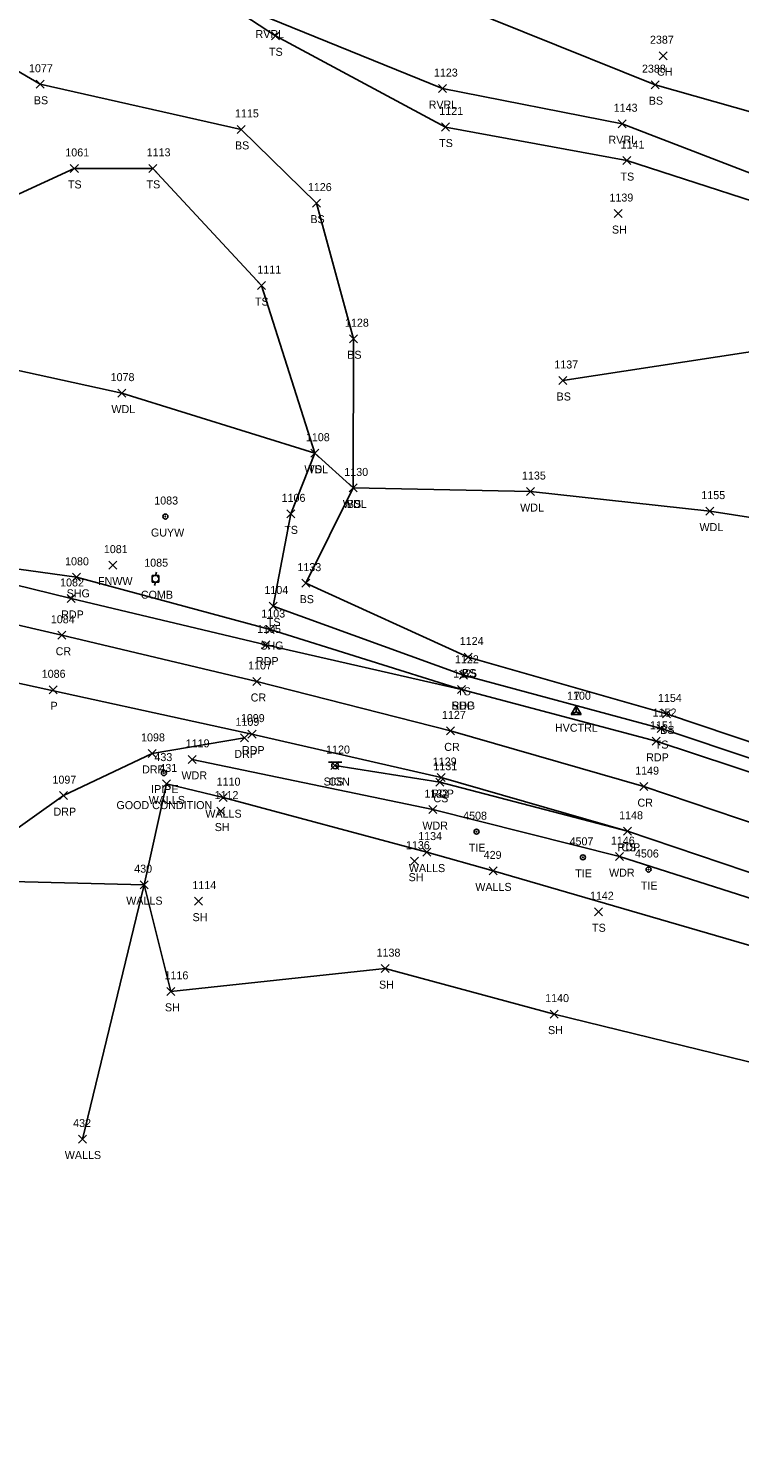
# Model space of a CAD drawing. Extents: x 1509053 to 1511576, y 400838 to 402572.
# Drawn here: x 1509252.8 to 1509430.5, y 401904.1 to 402256.5 of the extents above; entities that cross this region are included whole.
import ezdxf

# ---------------------------------------------------------------- set-up
doc = ezdxf.new("R2010")
doc.units = 0
for name, color, linetype in [('C_A', 7, 'Continuous'), ('C_I', 7, 'Continuous'), ('CBP', 7, 'Continuous'), ('CPSM', 7, 'Continuous'), ('D_A', 7, 'Continuous'), ('D_I', 7, 'Continuous'), ('D_TIC', 7, 'Continuous'), ('L_A', 7, 'Continuous'), ('L_I', 7, 'Continuous'), ('L_TIC', 7, 'Continuous'), ('LAWA', 7, 'Continuous'), ('LAWE', 7, 'Continuous'), ('LELB', 7, 'Continuous'), ('LSOGP', 7, 'Continuous'), ('LWS', 7, 'Continuous'), ('M_A', 7, 'Continuous'), ('M_C', 7, 'Continuous'), ('M_I', 7, 'Continuous'), ('MPIP', 7, 'Continuous'), ('P_A', 7, 'Continuous'), ('P_I', 7, 'Continuous'), ('P_TIC', 7, 'Continuous'), ('PET', 7, 'Continuous'), ('PRC', 7, 'Continuous'), ('PSU', 7, 'Continuous'), ('R_A', 7, 'Continuous'), ('R_I', 7, 'Continuous'), ('R_TIC', 7, 'Continuous'), ('RDP', 7, 'Continuous'), ('S_A', 7, 'Continuous'), ('S_I', 7, 'Continuous'), ('SSGN', 7, 'Continuous'), ('U_A', 7, 'Continuous'), ('U_I', 7, 'Continuous'), ('UP', 7, 'Continuous'), ('UPGW', 7, 'Continuous')]:
    doc.layers.add(name, color=color, linetype=linetype)

msp = doc.modelspace()

# ---------------------------------------------------------------- linework, layer by layer
at = {"layer": 'CBP'}
for centre, radius in [((1509364.72, 402055.77), 0.625), ((1509364.72, 402055.77), 0.0833), ((1509391.3, 402049.36), 0.625), ((1509391.3, 402049.36), 0.0833), ((1509407.68, 402046.32), 0.625), ((1509407.68, 402046.32), 0.0833)]:
    msp.add_circle(centre, radius, dxfattribs=at)
at = {"layer": 'CPSM'}
for p, q in [((1509388.37, 402085.02), (1509389.62, 402087.19)), ((1509388.37, 402085.02), (1509389.62, 402087.19)), ((1509388.37, 402085.02), (1509389.62, 402085.74)), ((1509388.37, 402085.02), (1509389.62, 402085.74)), ((1509388.37, 402085.02), (1509390.87, 402085.02)), ((1509388.37, 402085.02), (1509390.87, 402085.02)), ((1509390.87, 402085.02), (1509389.62, 402087.19)), ((1509389.62, 402085.74), (1509389.62, 402087.19)), ((1509390.87, 402085.02), (1509389.62, 402087.19)), ((1509389.62, 402085.74), (1509389.62, 402087.19)), ((1509389.62, 402085.74), (1509389.62, 402085.74)), ((1509389.62, 402085.74), (1509390.87, 402085.02)), ((1509389.62, 402085.74), (1509389.62, 402085.74)), ((1509389.62, 402085.74), (1509390.87, 402085.02))]:
    msp.add_line(p, q, dxfattribs=at)
at = {"layer": 'D_TIC'}
for points in [[(1509257.97, 402090.21), (1509259.97, 402092.22)], [(1509259.97, 402090.21), (1509257.97, 402092.22)]]:
    msp.add_lwpolyline(points, dxfattribs=at)
at = {"layer": 'L_TIC'}
for points in [[(1509313.5, 402253.64), (1509315.5, 402255.64)], [(1509315.5, 402253.64), (1509313.5, 402255.64)], [(1509410.3, 402248.66), (1509412.3, 402250.66)], [(1509412.3, 402248.66), (1509410.3, 402250.66)], [(1509254.73, 402241.53), (1509256.73, 402243.53)], [(1509256.73, 402241.53), (1509254.73, 402243.53)], [(1509355.2, 402240.45), (1509357.2, 402242.45)], [(1509357.2, 402240.45), (1509355.2, 402242.45)], [(1509408.3, 402241.42), (1509410.3, 402243.42)], [(1509410.3, 402241.42), (1509408.3, 402243.42)], [(1509304.95, 402230.25), (1509306.95, 402232.25)], [(1509306.95, 402230.25), (1509304.95, 402232.25)], [(1509355.98, 402230.85), (1509357.98, 402232.85)], [(1509357.98, 402230.85), (1509355.98, 402232.85)], [(1509400.11, 402231.66), (1509402.11, 402233.66)], [(1509402.11, 402231.66), (1509400.11, 402233.66)], [(1509263.28, 402220.5), (1509265.28, 402222.5)], [(1509265.28, 402220.5), (1509263.28, 402222.5)], [(1509282.91, 402220.52), (1509284.91, 402222.52)], [(1509284.91, 402220.52), (1509282.91, 402222.52)], [(1509401.27, 402222.46), (1509403.27, 402224.46)], [(1509403.27, 402222.46), (1509401.27, 402224.46)], [(1509323.79, 402211.83), (1509325.79, 402213.83)], [(1509325.79, 402211.83), (1509323.79, 402213.83)], [(1509399.06, 402209.22), (1509401.06, 402211.22)], [(1509401.06, 402209.22), (1509399.06, 402211.22)], [(1509309.99, 402191.23), (1509311.99, 402193.23)], [(1509311.99, 402191.23), (1509309.99, 402193.23)], [(1509333, 402177.95), (1509335, 402179.95)], [(1509335, 402177.95), (1509333, 402179.95)], [(1509385.28, 402167.51), (1509387.28, 402169.51)], [(1509387.28, 402167.51), (1509385.28, 402169.51)], [(1509275.13, 402164.35), (1509277.13, 402166.35)], [(1509277.13, 402164.35), (1509275.13, 402166.35)], [(1509323.31, 402149.34), (1509325.31, 402151.34)], [(1509325.31, 402149.34), (1509323.31, 402151.34)], [(1509323.31, 402149.34), (1509325.31, 402151.34)], [(1509325.31, 402149.34), (1509323.31, 402151.34)], [(1509332.92, 402140.66), (1509334.92, 402142.66)], [(1509334.92, 402140.66), (1509332.92, 402142.66)], [(1509332.92, 402140.66), (1509334.92, 402142.66)], [(1509334.92, 402140.66), (1509332.92, 402142.66)], [(1509377.2, 402139.76), (1509379.2, 402141.76)], [(1509379.2, 402139.76), (1509377.2, 402141.76)], [(1509421.99, 402134.87), (1509423.99, 402136.87)], [(1509423.99, 402134.87), (1509421.99, 402136.87)], [(1509317.31, 402134.19), (1509319.31, 402136.19)], [(1509319.31, 402134.19), (1509317.31, 402136.19)], [(1509272.86, 402121.37), (1509274.86, 402123.37)], [(1509274.86, 402121.37), (1509272.86, 402123.37)], [(1509321.11, 402116.87), (1509323.11, 402118.87)], [(1509323.11, 402116.87), (1509321.11, 402118.87)], [(1509312.95, 402111.16), (1509314.95, 402113.16)], [(1509314.95, 402111.16), (1509312.95, 402113.16)], [(1509361.66, 402098.41), (1509363.66, 402100.41)], [(1509363.66, 402098.41), (1509361.66, 402100.41)], [(1509360.47, 402093.85), (1509362.47, 402095.85)], [(1509362.47, 402093.85), (1509360.47, 402095.85)], [(1509411.17, 402084.19), (1509413.17, 402086.19)], [(1509413.17, 402084.19), (1509411.17, 402086.19)], [(1509409.83, 402080.54), (1509411.83, 402082.54)], [(1509411.83, 402080.54), (1509409.83, 402082.54)], [(1509292.68, 402072.84), (1509294.68, 402074.84)], [(1509294.68, 402072.84), (1509292.68, 402074.84)], [(1509328.37, 402071.3), (1509330.37, 402073.3)], [(1509330.37, 402071.3), (1509328.37, 402073.3)], [(1509286.3, 402066.7), (1509288.3, 402068.7)], [(1509288.3, 402066.7), (1509286.3, 402068.7)], [(1509354.52, 402067.12), (1509356.52, 402069.13)], [(1509356.52, 402067.12), (1509354.52, 402069.13)], [(1509300.46, 402063.27), (1509302.46, 402065.27)], [(1509302.46, 402063.27), (1509300.46, 402065.27)], [(1509299.87, 402059.92), (1509301.87, 402061.92)], [(1509301.87, 402059.92), (1509299.87, 402061.92)], [(1509352.84, 402060.29), (1509354.84, 402062.29)], [(1509354.84, 402060.29), (1509352.84, 402062.29)], [(1509401.46, 402054.88), (1509403.46, 402056.88)], [(1509403.46, 402054.88), (1509401.46, 402056.88)], [(1509348.27, 402047.4), (1509350.27, 402049.4)], [(1509350.27, 402047.4), (1509348.27, 402049.4)], [(1509351.28, 402049.67), (1509353.28, 402051.67)], [(1509353.28, 402049.67), (1509351.28, 402051.67)], [(1509399.46, 402048.53), (1509401.46, 402050.53)], [(1509401.46, 402048.53), (1509399.46, 402050.53)], [(1509367.88, 402044.97), (1509369.88, 402046.97)], [(1509369.88, 402044.97), (1509367.88, 402046.97)], [(1509280.69, 402041.53), (1509282.69, 402043.53)], [(1509282.69, 402041.53), (1509280.69, 402043.53)], [(1509280.69, 402041.53), (1509282.69, 402043.53)], [(1509282.69, 402041.53), (1509280.69, 402043.53)], [(1509294.32, 402037.41), (1509296.32, 402039.41)], [(1509296.32, 402037.41), (1509294.32, 402039.41)], [(1509394.17, 402034.76), (1509396.16, 402036.76)], [(1509396.16, 402034.76), (1509394.17, 402036.76)], [(1509340.88, 402020.55), (1509342.88, 402022.55)], [(1509342.88, 402020.55), (1509340.88, 402022.55)], [(1509287.42, 402014.87), (1509289.42, 402016.87)], [(1509289.42, 402014.87), (1509287.42, 402016.87)], [(1509383.09, 402009.19), (1509385.09, 402011.19)], [(1509385.09, 402009.19), (1509383.09, 402011.19)], [(1509265.34, 401977.97), (1509267.34, 401979.97)], [(1509267.34, 401977.97), (1509265.34, 401979.97)]]:
    msp.add_lwpolyline(points, dxfattribs=at)
at = {"layer": 'LAWA'}
for points in [[(1509076.57, 402183.15), (1509127.79, 402182.33), (1509173.6, 402169.45), (1509206.41, 402183.98), (1509219.47, 402177.73), (1509276.12, 402165.35), (1509324.31, 402150.34), (1509333.92, 402141.66), (1509378.2, 402140.76), (1509422.99, 402135.87), (1509484.22, 402126.37), (1509536.38, 402111.03), (1509587.67, 402075.95), (1509623.1, 402040.21), (1509661.3, 402001.82), (1509687.76, 401950.54), (1509742.09, 401890.27)], [(1509293.68, 402073.84), (1509353.84, 402061.29), (1509400.46, 402049.53), (1509447.87, 402034.45), (1509492.69, 402014.78), (1509536.64, 401993.35), (1509533.09, 401982.78), (1509551.67, 401951.95)]]:
    msp.add_lwpolyline(points, dxfattribs=at)
at = {"layer": 'LAWE'}
msp.add_lwpolyline([(1509105.87, 402324.24), (1509166.85, 402316.84), (1509211.49, 402305.13), (1509268.21, 402284.91), (1509312.96, 402259.07), (1509356.2, 402241.45), (1509401.11, 402232.66), (1509452.56, 402212.8), (1509514.16, 402192.04), (1509556.38, 402176.06), (1509631.87, 402126.97), (1509661.73, 402089.31), (1509701.86, 402034.14), (1509721.26, 402000.81), (1509742.13, 401921.74), (1509766.75, 401859.14), (1509782.51, 401819.75), (1509797.91, 401768.02), (1509814.1, 401723.17), (1509831.98, 401671.21)], dxfattribs=at)
at = {"layer": 'LELB'}
for points in [[(1509893.6, 401622.33), (1509860.64, 401660.7), (1509835.46, 401719.88), (1509820.45, 401775.67), (1509804.55, 401821.18), (1509793.58, 401877.47), (1509769.39, 401921.13), (1509750.31, 401995.31), (1509714.67, 402043.06), (1509675.87, 402101.28), (1509636.96, 402136.16), (1509603.47, 402183.37), (1509565.38, 402200.63), (1509506.19, 402219.72), (1509454.31, 402229.61), (1509409.3, 402242.42), (1509343.87, 402268.78), (1509286.85, 402299.31), (1509229.32, 402329.05), (1509168.38, 402334.88), (1509111.42, 402354.71)], [(1509268.21, 402284.91), (1509314.49, 402254.64), (1509356.98, 402231.85), (1509402.27, 402223.46), (1509451.09, 402207.68), (1509510.53, 402186.04), (1509553.53, 402174.63), (1509629.32, 402126.51), (1509658.3, 402084.82), (1509698.84, 402034.54), (1509720.34, 401997.13), (1509738.81, 401919.7), (1509762.85, 401861.64), (1509780.24, 401817.03), (1509795.72, 401767.1), (1509811.96, 401722.66)], [(1509236.36, 402253.91), (1509255.73, 402242.53)], [(1509305.96, 402231.25), (1509255.73, 402242.53)], [(1509305.96, 402231.25), (1509324.79, 402212.84), (1509334, 402178.95), (1509333.92, 402141.66), (1509322.11, 402117.87)], [(1509208.66, 402150.69), (1509219.47, 402177.73), (1509241.9, 402211.24), (1509264.28, 402221.5)], [(1509283.91, 402221.52), (1509264.28, 402221.5)], [(1509313.95, 402112.16), (1509318.31, 402135.19), (1509324.31, 402150.34), (1509310.99, 402192.23), (1509283.91, 402221.52)], [(1509386.28, 402168.51), (1509440.17, 402176.72), (1509501.07, 402173.56), (1509547.44, 402149.69), (1509608.94, 402102.89), (1509648.8, 402068.27), (1509684.12, 402026.81), (1509704.75, 401988.35), (1509738.81, 401919.7)], [(1509322.11, 402117.87), (1509362.66, 402099.41)], [(1509361.47, 402094.85), (1509313.95, 402112.16)], [(1509412.17, 402085.19), (1509362.66, 402099.41)], [(1509361.47, 402094.85), (1509410.83, 402081.54), (1509459.37, 402065.34), (1509506.44, 402045.45), (1509552.07, 402021.06), (1509595.83, 401996.62), (1509639.75, 401971.21), (1509681.43, 401940.52), (1509718.97, 401902.89)], [(1509412.17, 402085.19), (1509461.33, 402068.63), (1509508.93, 402048.3), (1509554.78, 402025.14), (1509598.01, 402000.86)], [(1509329.37, 402072.3), (1509355.52, 402068.12), (1509402.46, 402055.88)]]:
    msp.add_lwpolyline(points, dxfattribs=at)
at = {"layer": 'LSOGP'}
msp.add_lwpolyline([(1509231.98, 402043.7), (1509281.69, 402042.53), (1509288.42, 402015.87), (1509341.88, 402021.55), (1509384.08, 402010.19), (1509436.15, 401997.39)], dxfattribs=at)
at = {"layer": 'LWS'}
for points in [[(1509287.3, 402067.7), (1509281.69, 402042.53)], [(1509287.3, 402067.7), (1509301.46, 402064.27)], [(1509301.46, 402064.27), (1509352.28, 402050.67)], [(1509368.88, 402045.97), (1509352.28, 402050.67)], [(1509490.57, 402004.04), (1509440.68, 402025.04), (1509368.88, 402045.97)], [(1509281.69, 402042.53), (1509266.34, 401978.97)]]:
    msp.add_lwpolyline(points, dxfattribs=at)
at = {"layer": 'MPIP'}
for radius in [0.625, 0.0833]:
    msp.add_circle((1509286.64, 402070.41), radius, dxfattribs=at)
at = {"layer": 'P_TIC'}
for points in [[(1509263.83, 402118.33), (1509265.83, 402120.33)], [(1509265.83, 402118.33), (1509263.83, 402120.33)], [(1509262.51, 402113.05), (1509264.51, 402115.05)], [(1509264.51, 402113.05), (1509262.51, 402115.05)], [(1509260.18, 402103.85), (1509262.18, 402105.85)], [(1509262.18, 402103.85), (1509260.18, 402105.85)], [(1509312.18, 402105.28), (1509314.18, 402107.28)], [(1509314.18, 402105.28), (1509312.18, 402107.28)], [(1509311.14, 402101.42), (1509313.14, 402103.42)], [(1509313.14, 402101.42), (1509311.14, 402103.42)], [(1509308.89, 402092.3), (1509310.89, 402094.3)], [(1509310.89, 402092.3), (1509308.89, 402094.3)], [(1509360.01, 402090.29), (1509362.01, 402092.29)], [(1509362.01, 402090.29), (1509360.01, 402092.29)], [(1509360.01, 402090.29), (1509362.01, 402092.29)], [(1509362.01, 402090.29), (1509360.01, 402092.29)], [(1509307.65, 402079.15), (1509309.65, 402081.15)], [(1509309.65, 402079.15), (1509307.65, 402081.15)], [(1509357.23, 402079.96), (1509359.23, 402081.96)], [(1509359.23, 402079.96), (1509357.23, 402081.96)], [(1509408.6, 402077.35), (1509410.6, 402079.35)], [(1509410.6, 402077.35), (1509408.6, 402079.35)], [(1509354.93, 402068.3), (1509356.93, 402070.3)], [(1509356.93, 402068.3), (1509354.93, 402070.3)], [(1509405.48, 402066.02), (1509407.48, 402068.02)], [(1509407.48, 402066.02), (1509405.48, 402068.02)], [(1509401.46, 402054.88), (1509403.46, 402056.88)], [(1509403.46, 402054.88), (1509401.46, 402056.88)]]:
    msp.add_lwpolyline(points, dxfattribs=at)
at = {"layer": 'PET'}
for points in [[(1509069.74, 402162.61), (1509117.95, 402150.34), (1509166.31, 402138.6), (1509189.12, 402132.7), (1509214.97, 402125.92), (1509263.51, 402114.05), (1509312.14, 402102.42), (1509361.01, 402091.29), (1509409.6, 402078.35), (1509458.22, 402062.29), (1509505.25, 402041.71), (1509550.77, 402018.3), (1509593.93, 401993.28)], [(1509063.17, 402139.09), (1509112.19, 402126.33), (1509159.98, 402114.82), (1509209.05, 402103), (1509244.49, 402094.13), (1509308.65, 402080.15), (1509355.93, 402069.3), (1509402.46, 402055.88), (1509449.73, 402039.91), (1509495.54, 402020.72), (1509539.16, 401999.24), (1509581.25, 401974.02)]]:
    msp.add_lwpolyline(points, dxfattribs=at)
at = {"layer": 'PRC'}
msp.add_lwpolyline([(1509066.35, 402150.83), (1509115.03, 402139.18), (1509163.71, 402127.66), (1509212.43, 402116.11), (1509261.18, 402104.85), (1509309.89, 402093.3), (1509358.23, 402080.96), (1509406.48, 402067.02), (1509453.83, 402051.04), (1509500, 402031.81), (1509544.56, 402009.22), (1509587.94, 401984.24)], dxfattribs=at)
at = {"layer": 'PSU'}
msp.add_lwpolyline([(1509214.96, 402126.25), (1509264.82, 402119.33), (1509313.18, 402106.28), (1509361.01, 402091.29)], dxfattribs=at)
at = {"layer": 'R_TIC'}
for points in [[(1509305.74, 402078.22), (1509307.74, 402080.22)], [(1509307.74, 402078.22), (1509305.74, 402080.22)], [(1509282.73, 402074.33), (1509284.73, 402076.33)], [(1509284.73, 402074.33), (1509282.73, 402076.33)], [(1509260.59, 402063.77), (1509262.59, 402065.77)], [(1509262.59, 402063.77), (1509260.59, 402065.77)]]:
    msp.add_lwpolyline(points, dxfattribs=at)
at = {"layer": 'RDP'}
msp.add_lwpolyline([(1509231.98, 402043.7), (1509261.59, 402064.77), (1509283.73, 402075.33), (1509306.74, 402079.22)], dxfattribs=at)
at = {"layer": 'SSGN'}
for p, q in [((1509327.74, 402073.16), (1509331.08, 402073.16)), ((1509329.39, 402072.32), (1509329.39, 402072.32))]:
    msp.add_line(p, q, dxfattribs=at)
msp.add_circle((1509329.39, 402072.32), 0.833, dxfattribs=at)
at = {"layer": 'UP'}
for p, q in [((1509283.68, 402118.14), (1509283.68, 402119.81)), ((1509283.68, 402119.81), (1509285.35, 402119.81)), ((1509284.77, 402120.64), (1509284.52, 402119.81)), ((1509285.35, 402119.81), (1509285.35, 402118.14)), ((1509285.35, 402118.14), (1509283.68, 402118.14)), ((1509284.27, 402117.31), (1509284.52, 402118.14)), ((1509284.52, 402118.98), (1509284.52, 402118.98))]:
    msp.add_line(p, q, dxfattribs=at)
msp.add_circle((1509284.52, 402118.98), 0.833, dxfattribs=at)
at = {"layer": 'UPGW'}
for radius in [0.625, 0.0833]:
    msp.add_circle((1509287.02, 402134.52), radius, dxfattribs=at)

# ---------------------------------------------------------------- texts
at = {"layer": 'C_A'}
for s, p in [('HVCTRL', (1509384.31, 402080.74)), ('HVCTRL', (1509384.31, 402080.74)), ('TIE', (1509362.8, 402050.77)), ('TIE', (1509389.38, 402044.36)), ('TIE', (1509405.76, 402041.32))]:
    msp.add_text(s, height=2, dxfattribs=at).set_placement(p)
at = {"layer": 'C_I'}
for s, p in [('1100', (1509387.33, 402088.74)), ('7', (1509389.05, 402088.74)), ('4508', (1509361.38, 402058.77)), ('4507', (1509387.96, 402052.36)), ('4506', (1509404.29, 402049.32))]:
    msp.add_text(s, height=2, dxfattribs=at).set_placement(p)
at = {"layer": 'D_A'}
msp.add_text('P', height=2, dxfattribs=at).set_placement((1509258.34, 402086.22))
at = {"layer": 'D_I'}
msp.add_text('1086', height=2, dxfattribs=at).set_placement((1509256.14, 402094.22))
at = {"layer": 'L_A'}
for s, p in [('RVRL', (1509309.53, 402254.07)), ('TS', (1509312.9, 402249.64)), ('CH', (1509409.79, 402244.66)), ('BS', (1509254.17, 402237.53)), ('BS', (1509407.74, 402237.42)), ('RVRL', (1509352.77, 402236.45)), ('TS', (1509355.39, 402226.85)), ('RVRL', (1509397.68, 402227.66)), ('BS', (1509304.4, 402226.25)), ('TS', (1509262.69, 402216.5)), ('TS', (1509282.32, 402216.52)), ('TS', (1509400.68, 402218.46)), ('BS', (1509323.23, 402207.83)), ('SH', (1509398.54, 402205.22)), ('TS', (1509309.4, 402187.23)), ('BS', (1509332.44, 402173.94)), ('BS', (1509384.72, 402163.51)), ('WDL', (1509273.54, 402160.35)), ('WDL', (1509321.73, 402145.34)), ('TS', (1509322.72, 402145.34)), ('WDL', (1509331.34, 402136.66)), ('BS', (1509332.36, 402136.66)), ('WDL', (1509375.62, 402135.76)), ('TS', (1509316.72, 402130.19)), ('WDL', (1509420.41, 402130.87)), ('FNWW', (1509270.2, 402117.37)), ('BS', (1509320.55, 402112.87)), ('TS', (1509312.36, 402107.16)), ('BS', (1509361.1, 402094.41)), ('TS', (1509359.88, 402089.85)), ('BS', (1509410.61, 402080.19)), ('TS', (1509409.24, 402076.54)), ('WDR', (1509291.04, 402068.84)), ('CS', (1509327.81, 402067.3)), ('WALLS', (1509282.85, 402062.7)), ('CS', (1509353.96, 402063.12)), ('WALLS', (1509297, 402059.27)), ('SH', (1509299.36, 402055.92)), ('WDR', (1509351.2, 402056.29)), ('CS', (1509400.9, 402050.88)), ('WALLS', (1509347.82, 402045.67)), ('SH', (1509347.76, 402043.4)), ('WDR', (1509397.82, 402044.53)), ('WALLS', (1509364.42, 402040.97)), ('WALLS', (1509277.24, 402037.53)), ('WALLS', (1509277.24, 402037.53)), ('SH', (1509293.81, 402033.41)), ('TS', (1509393.57, 402030.76)), ('SH', (1509340.37, 402016.55)), ('SH', (1509286.91, 402010.87)), ('SH', (1509382.57, 402005.19)), ('WALLS', (1509261.89, 401973.97))]:
    msp.add_text(s, height=2, dxfattribs=at).set_placement(p)
at = {"layer": 'L_I'}
for s, p in [('2387', (1509408.04, 402252.66)), ('1077', (1509252.96, 402245.53)), ('1123', (1509354.08, 402244.45)), ('2388', (1509406.04, 402245.42)), ('1115', (1509304.4, 402234.25)), ('1121', (1509355.42, 402234.85)), ('1143', (1509398.98, 402235.66)), ('1141', (1509400.71, 402226.46)), ('1061', (1509262.03, 402224.5)), ('1113', (1509282.35, 402224.52)), ('1126', (1509322.61, 402215.84)), ('1139', (1509397.92, 402213.22)), ('1111', (1509309.99, 402195.23)), ('1128', (1509331.88, 402181.95)), ('1137', (1509384.15, 402171.51)), ('1078', (1509273.35, 402168.35)), ('1108', (1509322.11, 402153.34)), ('1108', (1509322.11, 402153.34)), ('1130', (1509331.71, 402144.66)), ('1130', (1509331.71, 402144.66)), ('1135', (1509376.08, 402143.76)), ('1106', (1509316.05, 402138.19)), ('1155', (1509420.87, 402138.87)), ('1081', (1509271.65, 402125.37)), ('1133', (1509319.99, 402120.87)), ('1104', (1509311.75, 402115.16)), ('1124', (1509360.53, 402102.41)), ('1122', (1509359.34, 402097.85)), ('1154', (1509410.04, 402088.19)), ('1152', (1509408.71, 402084.54)), ('1119', (1509292.11, 402076.84)), ('1120', (1509327.16, 402075.3)), ('431', (1509285.51, 402070.7)), ('1131', (1509353.96, 402071.12)), ('1110', (1509299.82, 402067.27)), ('1132', (1509351.71, 402064.29)), ('1112', (1509299.31, 402063.92)), ('1148', (1509400.34, 402058.88)), ('1134', (1509350.16, 402053.67)), ('1136', (1509347.09, 402051.4)), ('1146', (1509398.28, 402052.53)), ('429', (1509366.51, 402048.97)), ('430', (1509279.24, 402045.53)), ('430', (1509279.24, 402045.53)), ('1114', (1509293.76, 402041.41)), ('1142', (1509393.04, 402038.76)), ('1138', (1509339.76, 402024.55)), ('1116', (1509286.81, 402018.87)), ('1140', (1509381.87, 402013.19)), ('432', (1509263.98, 401981.97))]:
    msp.add_text(s, height=2, dxfattribs=at).set_placement(p)
at = {"layer": 'M_A'}
msp.add_text('IPIPE', height=2, dxfattribs=at).set_placement((1509283.47, 402065.41))
at = {"layer": 'M_C'}
msp.add_text('GOOD CONDITION', height=2, dxfattribs=at).set_placement((1509274.8, 402061.41))
at = {"layer": 'M_I'}
msp.add_text('433', height=2, dxfattribs=at).set_placement((1509284.28, 402073.41))
at = {"layer": 'P_A'}
for s, p in [('SHG', (1509262.36, 402114.33)), ('RDP', (1509260.99, 402109.05)), ('CR', (1509259.61, 402099.85)), ('SHG', (1509310.72, 402101.28)), ('RDP', (1509309.63, 402097.42)), ('CR', (1509308.32, 402088.3)), ('SHG', (1509358.55, 402086.29)), ('RDP', (1509358.5, 402086.29)), ('RDP', (1509306.14, 402075.15)), ('CR', (1509356.66, 402075.96)), ('RDP', (1509407.09, 402073.35)), ('RDP', (1509353.42, 402064.3)), ('CR', (1509404.92, 402062.02)), ('RDP', (1509399.95, 402050.88))]:
    msp.add_text(s, height=2, dxfattribs=at).set_placement(p)
at = {"layer": 'P_I'}
for s, p in [('1080', (1509261.97, 402122.33)), ('1082', (1509260.73, 402117.05)), ('1084', (1509258.41, 402107.85)), ('1103', (1509310.98, 402109.28)), ('1105', (1509309.93, 402105.42)), ('1107', (1509307.68, 402096.3)), ('1125', (1509358.89, 402094.29)), ('1125', (1509358.89, 402094.29)), ('1099', (1509305.87, 402083.15)), ('1127', (1509356.1, 402083.96)), ('1151', (1509408.04, 402081.35)), ('1129', (1509353.8, 402072.3)), ('1149', (1509404.35, 402070.02)), ('1148', (1509400.34, 402058.88))]:
    msp.add_text(s, height=2, dxfattribs=at).set_placement(p)
at = {"layer": 'R_A'}
for p in [(1509304.23, 402074.22), (1509281.21, 402070.33), (1509259.08, 402059.77)]:
    msp.add_text('DRP', height=2, dxfattribs=at).set_placement(p)
at = {"layer": 'R_I'}
for s, p in [('1109', (1509304.53, 402082.22)), ('1098', (1509280.95, 402078.33)), ('1097', (1509258.82, 402067.77))]:
    msp.add_text(s, height=2, dxfattribs=at).set_placement(p)
at = {"layer": 'S_A'}
msp.add_text('SIGN', height=2, dxfattribs=at).set_placement((1509326.53, 402067.3))
at = {"layer": 'S_I'}
msp.add_text('1120', height=2, dxfattribs=at).set_placement((1509327.16, 402075.3))
at = {"layer": 'U_A'}
for s, p in [('GUYW', (1509283.41, 402129.52)), ('COMB', (1509280.9, 402113.98))]:
    msp.add_text(s, height=2, dxfattribs=at).set_placement(p)
at = {"layer": 'U_I'}
for s, p in [('1083', (1509284.24, 402137.52)), ('1085', (1509281.74, 402121.98))]:
    msp.add_text(s, height=2, dxfattribs=at).set_placement(p)

doc.saveas('drawing.dxf')
